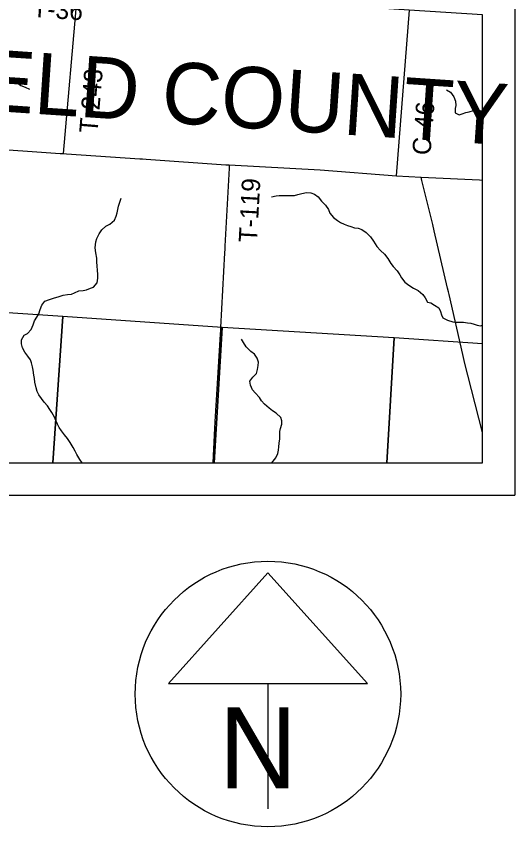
# Model space of a CAD drawing. Extents: x 0 to 34, y 0 to 22.
# Drawn here: x 7.46 to 9, y 12.976 to 15.479 of the extents above; entities that cross this region are included whole.
import ezdxf

# ---------------------------------------------------------------- set-up
doc = ezdxf.new("R2010")
doc.units = 0
for name, color, linetype in [('GM_X_Corporation', 7, 'Continuous'), ('GM_X_County_Road', 7, 'Continuous'), ('GM_X_County_Road_Text', 7, 'Continuous'), ('GM_X_County_Text', 7, 'Continuous'), ('GM_X_Minor_River', 7, 'Continuous'), ('GM_X_Township_Road', 7, 'Continuous'), ('GM_X_Township_Road_Text', 7, 'Continuous'), ('GM_X_Unincorporated_Text', 7, 'Continuous'), ('SH_Cut_Line', 7, 'Continuous'), ('SH_Data', 7, 'Continuous'), ('SH_Masking', 7, 'Continuous'), ('SH_Text', 7, 'Continuous')]:
    doc.layers.add(name, color=color, linetype=linetype)

msp = doc.modelspace()

# ---------------------------------------------------------------- linework, layer by layer
at = {"layer": 'GM_X_Corporation'}
msp.add_lwpolyline([(4.9875, 14.1), (8.9, 14.1), (8.9, 15.4827), (8.6741, 15.4976), (7.6503, 15.5653), (6.838, 15.6206), (6.624, 15.6351), (6.4, 15.6498), (6.1109, 15.6683), (5.9419, 15.6782), (5.0952, 15.7318), (5.0611, 15.2147)], close=True, dxfattribs=at)
at = {"layer": 'GM_X_County_Road'}
for q in [(8.6744, 15.4971), (8.7104, 14.9817)]:
    msp.add_line((8.635, 14.9861), q, dxfattribs=at)
for points in [[(6.0671, 15.1581), (6.5033, 15.13), (6.9303, 15.1012), (6.9673, 15.0987), (7.0963, 15.09), (7.1532, 15.0863), (7.3292, 15.0734), (7.3386, 15.0729), (7.3489, 15.0722), (7.5961, 15.0553), (7.606, 15.0546), (7.6158, 15.0539), (7.8422, 15.0387), (7.8505, 15.0381), (7.8619, 15.0373), (8.1079, 15.0203), (8.1178, 15.0196), (8.3992, 15.0045), (8.635, 14.9861)], [(8.9, 14.194), (8.8438, 14.4144), (8.8433, 14.4163), (8.8393, 14.434), (8.7968, 14.6201), (8.795, 14.6281), (8.7923, 14.6396), (8.7514, 14.8158), (8.7466, 14.8353), (8.7129, 14.9719), (8.7104, 14.9817)], [(8.7104, 14.9817), (8.733, 14.9806), (8.8913, 14.9733), (8.9, 14.9729)]]:
    msp.add_lwpolyline(points, dxfattribs=at)
at = {"layer": 'GM_X_Minor_River'}
for points in [[(7.4501, 15.2801), (7.4626, 15.2735), (7.4746, 15.2646), (7.4874, 15.2595), (7.5006, 15.2537)], [(8.7893, 15.252), (8.801, 15.2443), (8.8114, 15.2302), (8.817, 15.2164), (8.818, 15.2035), (8.816, 15.1937), (8.8162, 15.1811), (8.8283, 15.1749), (8.8378, 15.1779), (8.8484, 15.1816), (8.8594, 15.1837), (8.872, 15.1878), (8.8856, 15.1903), (8.8985, 15.1856), (8.9, 15.1843)], [(8.249, 14.9217), (8.2627, 14.9242), (8.2721, 14.9249), (8.282, 14.9252), (8.3093, 14.9249), (8.3199, 14.9251), (8.3297, 14.9281), (8.3423, 14.9317), (8.3563, 14.935), (8.3703, 14.9337), (8.3809, 14.9291), (8.3929, 14.9213), (8.4034, 14.9076), (8.4158, 14.8957), (8.4243, 14.8823), (8.4288, 14.8705), (8.44, 14.8571), (8.452, 14.8486), (8.4618, 14.8424), (8.4731, 14.837), (8.4833, 14.8327), (8.4939, 14.83), (8.5052, 14.826), (8.5158, 14.824), (8.5271, 14.8205), (8.541, 14.8112), (8.5541, 14.7978), (8.5634, 14.7844), (8.5735, 14.7676), (8.5855, 14.755), (8.5979, 14.7438), (8.6083, 14.7308), (8.6176, 14.7152), (8.6247, 14.7056), (8.6371, 14.693), (8.6449, 14.6807), (8.6501, 14.6712), (8.6606, 14.6578), (8.6722, 14.6482), (8.6876, 14.6389), (8.7012, 14.6316), (8.7155, 14.6196), (8.7229, 14.6097), (8.7304, 14.596), (8.7406, 14.5943), (8.7522, 14.5862), (8.765, 14.5781), (8.7706, 14.5671), (8.7731, 14.5568), (8.7779, 14.5473), (8.7923, 14.5407), (8.8085, 14.5352), (8.8187, 14.5343), (8.8418, 14.5341), (8.8536, 14.5324), (8.8641, 14.5308), (8.874, 14.5284), (8.8842, 14.5249), (8.8944, 14.5225), (8.9, 14.5246)], [(7.578, 14.241), (7.5698, 14.2551), (7.5635, 14.265), (7.5568, 14.2761), (7.5463, 14.2876), (7.5381, 14.2983), (7.5299, 14.3102), (7.525, 14.3197), (7.5218, 14.3319), (7.5178, 14.3494), (7.516, 14.3604), (7.5146, 14.371), (7.5121, 14.3859), (7.51, 14.3965), (7.5071, 14.4083), (7.5041, 14.4178), (7.4959, 14.4293), (7.487, 14.4415), (7.4799, 14.4545), (7.4763, 14.4678), (7.4764, 14.48), (7.4849, 14.4936), (7.4944, 14.4995), (7.5063, 14.5119), (7.5125, 14.5263), (7.5164, 14.5384), (7.5237, 14.5493), (7.5299, 14.5603), (7.5338, 14.5731), (7.5389, 14.5868), (7.5485, 14.5988), (7.5626, 14.6047), (7.5747, 14.608), (7.5926, 14.6135), (7.6048, 14.6179), (7.618, 14.6193), (7.6306, 14.6203), (7.6405, 14.6252), (7.6534, 14.6311), (7.6667, 14.6317), (7.6769, 14.6343), (7.6891, 14.6395), (7.6986, 14.6424), (7.7097, 14.6552), (7.7122, 14.6703), (7.7119, 14.6817), (7.7109, 14.6943), (7.7099, 14.7076), (7.7093, 14.7205), (7.7087, 14.7323), (7.7058, 14.7486), (7.7041, 14.7634), (7.7058, 14.7824), (7.7086, 14.7926), (7.7159, 14.807), (7.7248, 14.8194), (7.737, 14.831), (7.7488, 14.8366), (7.7637, 14.849), (7.7692, 14.8618), (7.7715, 14.8717), (7.7739, 14.8819), (7.7763, 14.8929), (7.7802, 14.905), (7.7845, 14.9171)], [(8.2495, 14.1), (8.2623, 14.1154), (8.2685, 14.1286), (8.2697, 14.1385), (8.2714, 14.1491), (8.2722, 14.1605), (8.2739, 14.1741), (8.274, 14.187), (8.2741, 14.1965), (8.2758, 14.2063), (8.2801, 14.2192), (8.2806, 14.2298), (8.2773, 14.2394), (8.2634, 14.2528), (8.2517, 14.2609), (8.2412, 14.2686), (8.2273, 14.2812), (8.218, 14.2916), (8.2113, 14.3015), (8.1985, 14.3161), (8.1899, 14.3257), (8.1833, 14.3398), (8.1819, 14.3516), (8.1911, 14.3644), (8.2022, 14.3756), (8.2057, 14.3881), (8.2074, 14.4002), (8.2079, 14.4112), (8.2046, 14.4227), (8.1957, 14.4357), (8.1848, 14.4441), (8.1705, 14.4583), (8.1619, 14.4717), (8.156, 14.482)], [(7.6638, 14.1), (7.6561, 14.1103), (7.6476, 14.1252), (7.6424, 14.1359), (7.6361, 14.1477), (7.6264, 14.1626), (7.6186, 14.1745), (7.6092, 14.1864), (7.5995, 14.1986), (7.5924, 14.2089), (7.5876, 14.2196), (7.5824, 14.231), (7.578, 14.241)]]:
    msp.add_lwpolyline(points, dxfattribs=at)
at = {"layer": 'GM_X_Township_Road'}
msp.add_line((7.606, 15.0546), (7.6505, 15.5648), dxfattribs=at)
msp.add_lwpolyline([(8.1178, 15.0196), (8.1173, 15.0095), (8.1045, 14.7686), (8.104, 14.7594), (8.1034, 14.7485), (8.0913, 14.5176), (8.0909, 14.5097), (8.0901, 14.4975), (8.0737, 14.2266), (8.0736, 14.225), (8.0726, 14.2065), (8.0669, 14.1)], dxfattribs=at)
at = {"layer": 'GM_X_Unincorporated_Text'}
for points in [[(7.0331, 14.1), (7.5731, 14.1), (7.6037, 14.5512), (7.0634, 14.5876)], [(7.5731, 14.1), (8.0711, 14.1), (8.096, 14.5173), (7.6037, 14.5512)], [(8.0711, 14.1), (8.6046, 14.1), (8.6276, 14.4861), (8.096, 14.5173)], [(8.6046, 14.1), (8.9, 14.1), (8.9, 14.4675), (8.6276, 14.4861)]]:
    msp.add_lwpolyline(points, close=True, dxfattribs=at)
at = {"layer": 'SH_Cut_Line'}
msp.add_lwpolyline([(2.1, 15.9442), (2.1, 14.1), (8.9, 14.1), (8.9, 15.4827), (8.6741, 15.4976), (7.6503, 15.5653), (6.838, 15.6206), (6.624, 15.6351), (6.4, 15.6498), (6.1109, 15.6683), (5.9419, 15.6782), (5.0952, 15.7318), (4.92, 15.7429), (4.5905, 15.7634), (4.2803, 15.787), (3.9945, 15.8088), (3.3132, 15.8609), (2.8362, 15.8952), (2.7799, 15.8989), (2.6921, 15.9056), (2.5827, 15.9132), (2.2903, 15.9292)], close=True, dxfattribs=at)
at = {"layer": 'SH_Data'}
for p in [(9, 21), (2, 14)]:
    msp.add_line(p, (9, 14), dxfattribs=at)
at = {"layer": 'SH_Masking'}
msp.add_circle((8.2375, 13.386), 0.41, dxfattribs=at)
at = {"layer": 'SH_Text'}
for p, q in [((8.2375, 13.7598), (7.9299, 13.4185)), ((8.545, 13.4185), (8.2375, 13.7598)), ((7.9299, 13.4185), (8.545, 13.4185)), ((8.2375, 13.4185), (8.2375, 13.0318))]:
    msp.add_line(p, q, dxfattribs=at)
msp.add_circle((8.2375, 13.386), 0.41, dxfattribs=at)

# ---------------------------------------------------------------- texts
at = {"layer": 'GM_X_County_Road_Text'}
msp.add_text('C-46', height=0.05682, rotation=85.5486, dxfattribs=at).set_placement((8.7395, 15.0483))
at = {"layer": 'GM_X_County_Text'}
msp.add_text('FAIRFIELD COUNTY', height=0.189394, rotation=356.1646, dxfattribs=at).set_placement((6.5431, 15.243))
at = {"layer": 'GM_X_Township_Road_Text'}
for s, rotation, p in [('T-36', 356.115, (7.5085, 15.4767)), ('T-243', 85.2357, (7.711, 15.1161)), ('T-119', 86.9131, (8.2037, 14.779))]:
    msp.add_text(s, height=0.05682, rotation=rotation, dxfattribs=at).set_placement(p)
at = {"layer": 'SH_Text'}
msp.add_text('N', height=0.25, rotation=360, dxfattribs=at).set_placement((8.0862, 13.0947))

doc.saveas('drawing.dxf')
